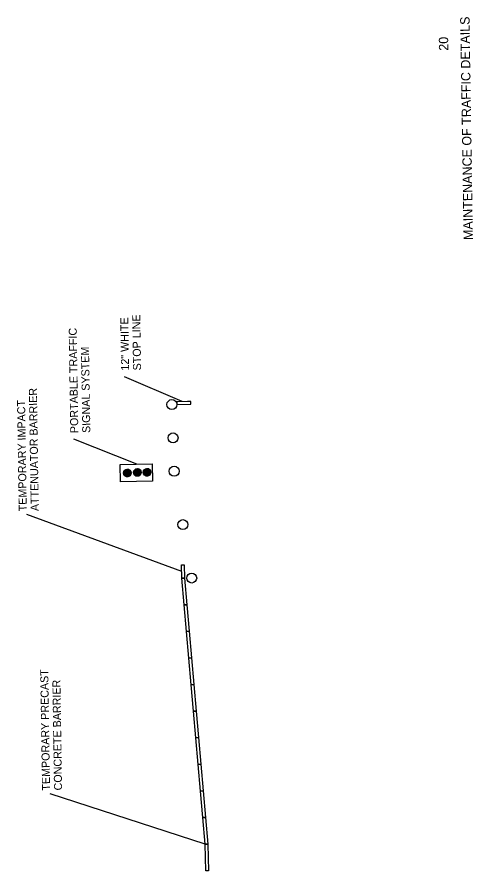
# Model space of a CAD drawing. Extents: x 1770018 to 1773492, y 718230 to 729141.
# Drawn here: x 1770018 to 1770360, y 724961 to 725601 of the extents above; entities that cross this region are included whole.
import ezdxf

# ---------------------------------------------------------------- set-up
doc = ezdxf.new("R2010")
doc.units = 0
for name, color, linetype in [('Default', 7, 'Continuous'), ('R_Border', 7, 'Continuous'), ('R_Dimension', 7, 'Continuous'), ('R_MOT', 7, 'Continuous'), ('R_Striping', 7, 'Continuous'), ('T_Vehicle Path Rt', 7, 'Continuous')]:
    doc.layers.add(name, color=color, linetype=linetype)

msp = doc.modelspace()

# ---------------------------------------------------------------- linework, layer by layer
at = {"layer": 'Default'}
for p, q in [((1770101.02, 725256.34), (1770097.97, 725259.3)), ((1770100.84, 725256.33), (1770097.97, 725259.12)), ((1770101.18, 725256.35), (1770097.98, 725259.46)), ((1770100.66, 725256.34), (1770097.98, 725258.94)), ((1770101.34, 725256.38), (1770097.99, 725259.62)), ((1770100.46, 725256.36), (1770098, 725258.74)), ((1770101.48, 725256.41), (1770098.02, 725259.77)), ((1770101.63, 725256.44), (1770098.05, 725259.91)), ((1770100.24, 725256.4), (1770098.05, 725258.52)), ((1770101.76, 725256.49), (1770098.09, 725260.05)), ((1770099.99, 725256.46), (1770098.12, 725258.28)), ((1770101.89, 725256.53), (1770098.13, 725260.18)), ((1770102.02, 725256.59), (1770098.18, 725260.31)), ((1770102.14, 725256.64), (1770098.24, 725260.43)), ((1770102.25, 725256.71), (1770098.29, 725260.55)), ((1770102.37, 725256.77), (1770098.36, 725260.66)), ((1770102.47, 725256.84), (1770098.42, 725260.77)), ((1770102.58, 725256.92), (1770098.5, 725260.87)), ((1770102.67, 725256.99), (1770098.57, 725260.97)), ((1770102.77, 725257.08), (1770098.65, 725261.07)), ((1770102.86, 725257.16), (1770098.73, 725261.16)), ((1770102.95, 725257.25), (1770098.82, 725261.25)), ((1770103.03, 725257.35), (1770098.91, 725261.34)), ((1770103.11, 725257.44), (1770099.01, 725261.42)), ((1770103.18, 725257.54), (1770099.1, 725261.5)), ((1770103.26, 725257.65), (1770099.21, 725261.58)), ((1770103.32, 725257.76), (1770099.31, 725261.65)), ((1770103.38, 725257.87), (1770099.43, 725261.71)), ((1770103.44, 725257.99), (1770099.54, 725261.77)), ((1770103.5, 725258.11), (1770099.66, 725261.83)), ((1770103.55, 725258.24), (1770099.79, 725261.88)), ((1770103.59, 725258.37), (1770099.92, 725261.93)), ((1770103.63, 725258.51), (1770100.05, 725261.97)), ((1770103.66, 725258.65), (1770100.2, 725262.01)), ((1770103.69, 725258.8), (1770100.34, 725262.04)), ((1770103.7, 725258.96), (1770100.5, 725262.06)), ((1770103.71, 725259.12), (1770100.66, 725262.08)), ((1770103.71, 725259.3), (1770100.84, 725262.08)), ((1770103.7, 725259.48), (1770101.02, 725262.08)), ((1770103.68, 725259.68), (1770101.22, 725262.06)), ((1770103.63, 725259.9), (1770101.44, 725262.02)), ((1770103.56, 725260.14), (1770101.69, 725261.95)), ((1770103.44, 725260.43), (1770101.98, 725261.85)), ((1770103.22, 725260.82), (1770102.37, 725261.64)), ((1770108.5, 725256.72), (1770105.45, 725259.68)), ((1770108.32, 725256.71), (1770105.45, 725259.5)), ((1770108.66, 725256.73), (1770105.46, 725259.84)), ((1770108.14, 725256.72), (1770105.46, 725259.32)), ((1770108.82, 725256.76), (1770105.47, 725260)), ((1770107.94, 725256.74), (1770105.48, 725259.12)), ((1770108.96, 725256.79), (1770105.5, 725260.15)), ((1770109.11, 725256.82), (1770105.53, 725260.29)), ((1770107.72, 725256.78), (1770105.53, 725258.9)), ((1770109.24, 725256.86), (1770105.57, 725260.43)), ((1770107.47, 725256.84), (1770105.6, 725258.66)), ((1770109.37, 725256.91), (1770105.61, 725260.56)), ((1770109.5, 725256.96), (1770105.66, 725260.68)), ((1770109.62, 725257.02), (1770105.72, 725260.81)), ((1770107.18, 725256.95), (1770105.72, 725258.37)), ((1770109.73, 725257.08), (1770105.77, 725260.92)), ((1770109.85, 725257.15), (1770105.84, 725261.04)), ((1770109.95, 725257.22), (1770105.9, 725261.15)), ((1770110.06, 725257.3), (1770105.98, 725261.25)), ((1770110.15, 725257.37), (1770106.05, 725261.35)), ((1770110.25, 725257.46), (1770106.13, 725261.45)), ((1770110.34, 725257.54), (1770106.21, 725261.54)), ((1770110.43, 725257.63), (1770106.3, 725261.63)), ((1770110.51, 725257.72), (1770106.39, 725261.72)), ((1770110.59, 725257.82), (1770106.49, 725261.8)), ((1770110.66, 725257.92), (1770106.58, 725261.88)), ((1770110.74, 725258.03), (1770106.69, 725261.95)), ((1770110.8, 725258.14), (1770106.79, 725262.02)), ((1770110.87, 725258.25), (1770106.91, 725262.09)), ((1770110.92, 725258.37), (1770107.02, 725262.15)), ((1770110.98, 725258.49), (1770107.14, 725262.21)), ((1770111.03, 725258.62), (1770107.27, 725262.26)), ((1770111.07, 725258.75), (1770107.4, 725262.31)), ((1770111.11, 725258.89), (1770107.53, 725262.35)), ((1770111.14, 725259.03), (1770107.68, 725262.39)), ((1770111.17, 725259.18), (1770107.82, 725262.42)), ((1770111.18, 725259.34), (1770107.98, 725262.44)), ((1770111.19, 725259.5), (1770108.14, 725262.46)), ((1770111.19, 725259.67), (1770108.32, 725262.46)), ((1770111.18, 725259.86), (1770108.5, 725262.46)), ((1770111.16, 725260.06), (1770108.7, 725262.44)), ((1770111.11, 725260.28), (1770108.92, 725262.4)), ((1770111.04, 725260.52), (1770109.17, 725262.33)), ((1770110.92, 725260.81), (1770109.46, 725262.23)), ((1770110.7, 725261.19), (1770109.85, 725262.02)), ((1770115.67, 725256.83), (1770112.71, 725259.69)), ((1770115.84, 725256.83), (1770112.72, 725259.86)), ((1770115.49, 725256.83), (1770112.72, 725259.51)), ((1770116, 725256.85), (1770112.73, 725260.02)), ((1770115.3, 725256.84), (1770112.74, 725259.32)), ((1770116.15, 725256.88), (1770112.75, 725260.18)), ((1770115.09, 725256.87), (1770112.77, 725259.11)), ((1770116.3, 725256.91), (1770112.78, 725260.32)), ((1770116.44, 725256.95), (1770112.82, 725260.46)), ((1770114.85, 725256.92), (1770112.83, 725258.88)), ((1770116.57, 725257), (1770112.86, 725260.6)), ((1770116.7, 725257.05), (1770112.9, 725260.73)), ((1770114.59, 725257), (1770112.93, 725258.62)), ((1770116.82, 725257.1), (1770112.95, 725260.85)), ((1770116.94, 725257.16), (1770113.01, 725260.97)), ((1770117.05, 725257.22), (1770113.07, 725261.09)), ((1770114.26, 725257.15), (1770113.08, 725258.29)), ((1770117.16, 725257.29), (1770113.14, 725261.2)), ((1770117.27, 725257.37), (1770113.2, 725261.31)), ((1770117.37, 725257.44), (1770113.28, 725261.41)), ((1770117.47, 725257.52), (1770113.35, 725261.51)), ((1770117.56, 725257.61), (1770113.44, 725261.6)), ((1770117.65, 725257.69), (1770113.52, 725261.7)), ((1770117.73, 725257.78), (1770113.61, 725261.78)), ((1770117.81, 725257.88), (1770113.7, 725261.87)), ((1770117.89, 725257.98), (1770113.8, 725261.95)), ((1770117.97, 725258.08), (1770113.9, 725262.02)), ((1770118.03, 725258.19), (1770114, 725262.1)), ((1770118.1, 725258.3), (1770114.11, 725262.17)), ((1770118.16, 725258.41), (1770114.23, 725262.23)), ((1770118.22, 725258.53), (1770114.34, 725262.29)), ((1770118.31, 725258.79), (1770114.59, 725262.4)), ((1770118.36, 725258.92), (1770114.73, 725262.44)), ((1770118.39, 725259.06), (1770114.86, 725262.48)), ((1770118.42, 725259.21), (1770115.01, 725262.51)), ((1770118.44, 725259.36), (1770115.16, 725262.54)), ((1770118.46, 725259.52), (1770115.32, 725262.56)), ((1770118.46, 725259.69), (1770115.49, 725262.57)), ((1770118.46, 725259.87), (1770115.67, 725262.57)), ((1770118.44, 725260.06), (1770115.86, 725262.56)), ((1770118.41, 725260.26), (1770116.07, 725262.53)), ((1770118.35, 725260.49), (1770116.3, 725262.48)), ((1770118.26, 725260.75), (1770116.56, 725262.4)), ((1770118.12, 725261.07), (1770116.88, 725262.27)), ((1770099.7, 725256.57), (1770098.23, 725257.99)), ((1770099.31, 725256.77), (1770098.45, 725257.61)), ((1770106.79, 725257.15), (1770105.93, 725257.98))]:
    msp.add_line(p, q, dxfattribs=at)
msp.add_lwpolyline([(1770095.71, 725252.7), (1770095.51, 725265.69), (1770119.48, 725266.06), (1770119.68, 725253.07)], close=True, dxfattribs=at)
for centre in [(1770100.84, 725259.21), (1770108.32, 725259.59), (1770115.59, 725259.7)]:
    msp.add_circle(centre, 2.87, dxfattribs=at)
at = {"layer": 'R_Dimension'}
for p, q in [((1770141.86, 725312.69), (1770098.65, 725331.33)), ((1770107.81, 725265.88), (1770060.59, 725284.46)), ((1770141.53, 725185.41), (1770025.49, 725228.02))]:
    msp.add_line(p, q, dxfattribs=at)
msp.add_lwpolyline([(1770159, 724981.05), (1770042.94, 725018.75)], dxfattribs=at)
at = {"layer": 'R_MOT'}
for centre in [(1770134.18, 725310.47), (1770135.03, 725285.49), (1770135.88, 725260.5), (1770142.44, 725220.51), (1770148.99, 725180.52)]:
    msp.add_circle(centre, 3.75, dxfattribs=at)
at = {"layer": 'R_Striping'}
for p, q in [((1770137.85, 725312.63), (1770137.91, 725310.9)), ((1770137.91, 725310.9), (1770137.91, 725310.89)), ((1770137.93, 725310.63), (1770148.44, 725310.79)), ((1770148.44, 725310.79), (1770148.4, 725312.79))]:
    msp.add_line(p, q, dxfattribs=at)
msp.add_lwpolyline([(1770148.4, 725312.79), (1770145.87, 725312.75), (1770137.85, 725312.63)], dxfattribs=at)
for start, end in [(2.93525, 6.53038), (2.55633, 2.74579), (2.55633, 2.74579)]:
    msp.add_arc((1770134.18, 725310.47), 3.75, start, end, dxfattribs=at)
at = {"layer": 'T_Vehicle Path Rt'}
for points in [[(1770141.67, 725180.41), (1770141.39, 725190.41), (1770143.39, 725190.46), (1770143.67, 725180.47)], [(1770143.41, 725160.37), (1770141.68, 725180.29), (1770143.67, 725180.47), (1770145.4, 725160.54)], [(1770145.14, 725140.44), (1770143.41, 725160.37), (1770145.4, 725160.54), (1770147.13, 725140.62)], [(1770146.87, 725120.52), (1770145.14, 725140.44), (1770147.13, 725140.62), (1770148.87, 725120.69)], [(1770148.61, 725100.59), (1770146.87, 725120.52), (1770148.87, 725120.69), (1770150.6, 725100.77)], [(1770150.34, 725080.67), (1770148.61, 725100.59), (1770150.6, 725100.77), (1770152.33, 725080.84)], [(1770152.07, 725060.75), (1770150.34, 725080.67), (1770152.33, 725080.84), (1770154.06, 725060.92)], [(1770153.8, 725040.82), (1770152.07, 725060.75), (1770154.06, 725060.92), (1770155.8, 725040.99)], [(1770155.54, 725020.9), (1770153.8, 725040.82), (1770155.8, 725040.99), (1770157.53, 725021.07)], [(1770157.27, 725000.97), (1770155.54, 725020.9), (1770157.53, 725021.07), (1770159.26, 725001.14)], [(1770159, 724981.05), (1770157.27, 725000.97), (1770159.26, 725001.14), (1770160.99, 724981.22)], [(1770159.64, 724961.06), (1770159, 724981.05), (1770161, 724981.11), (1770161.64, 724961.12)]]:
    msp.add_lwpolyline(points, close=True, dxfattribs=at)

# ---------------------------------------------------------------- texts
at = {"layer": 'R_Border'}
for s, p in [('MAINTENANCE OF TRAFFIC DETAILS', (1770359.81, 725433.81)), ('20', (1770341.36, 725575.66))]:
    msp.add_text(s, height=7, rotation=90.88269, dxfattribs=at).set_placement(p)
at = {"layer": 'R_Dimension'}
for s, p in [('12" WHITE', (1770102.09, 725335.98)), ('STOP LINE', (1770111.08, 725336.12)), ('PORTABLE TRAFFIC', (1770064.02, 725289.11)), ('SIGNAL SYSTEM', (1770073.02, 725289.25)), ('ATTENUATOR BARRIER', (1770034.4, 725230.69)), ('TEMPORARY IMPACT', (1770025.4, 725230.56)), ('TEMPORARY PRECAST', (1770042.86, 725021.28)), ('CONCRETE BARRIER', (1770051.85, 725021.42))]:
    msp.add_text(s, height=6, rotation=90.88269, dxfattribs=at).set_placement(p)

doc.saveas('drawing.dxf')
